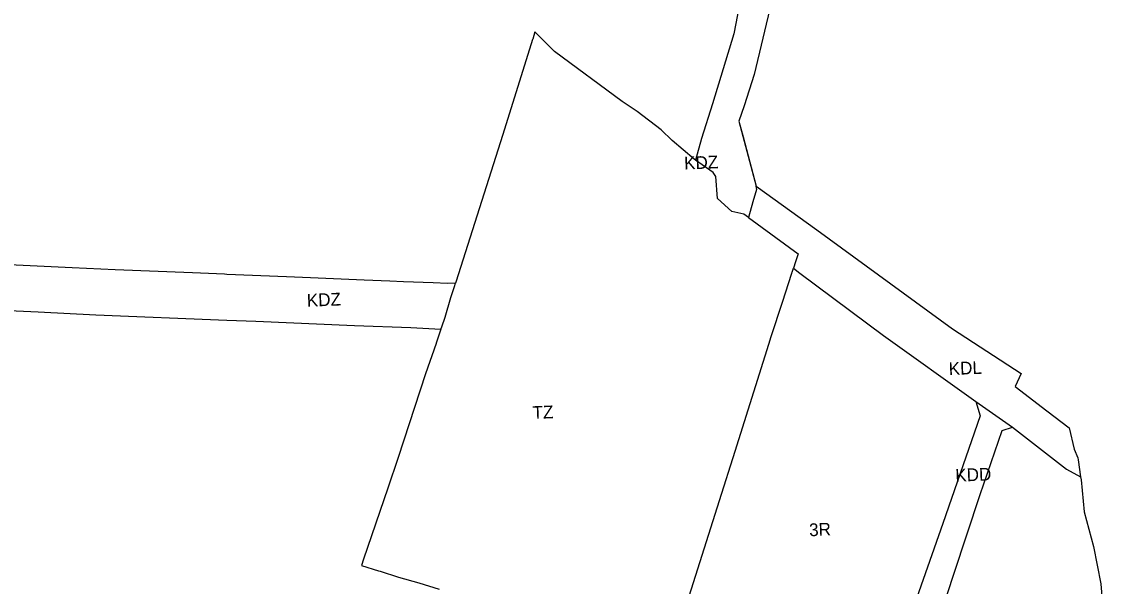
# Model space of a CAD drawing. Extents: x 7417062 to 7419348, y 5549957 to 5551711.
# Drawn here: x 7418374 to 7418967, y 5550811 to 5551121 of the extents above; entities that cross this region are included whole.
import ezdxf

# ---------------------------------------------------------------- set-up
doc = ezdxf.new("R2010")
doc.units = 0
for name, color, linetype in [('GRANICA_PLANU_po_wejsciu_MYDLNIKI', 7, 'Continuous'), ('linie_rozgraniczające_po_wejsciu_MYDLNIKI', 7, 'Continuous'), ('oznaczenia_przeznaczen_po_wejsciu_MYDLNIKI', 7, 'Continuous')]:
    doc.layers.add(name, color=color, linetype=linetype)

msp = doc.modelspace()

# ---------------------------------------------------------------- linework, layer by layer
at = {"layer": 'GRANICA_PLANU_po_wejsciu_MYDLNIKI'}
msp.add_lwpolyline([(7418785.33, 5551131.44), (7418775.9, 5551091.48), (7418770.4, 5551074.37), (7418767.45, 5551065.94), (7418769.76, 5551057.22), (7418776.89, 5551030.31), (7418776.92, 5551030.17), (7418810.32, 5551006.33), (7418884.63, 5550951.85), (7418922.29, 5550927.45), (7418919.04, 5550920.35), (7418936.52, 5550906.96), (7418948.63, 5550897.68), (7418951.38, 5550885.85), (7418953.53, 5550881.09), (7418953.68, 5550880.07), (7418955.01, 5550870.78), (7418955.26, 5550869.02), (7418957.01, 5550851.46), (7418962.06, 5550832.43), (7418966.12, 5550812.07), (7418966.93, 5550800.53)], dxfattribs=at)
at = {"layer": 'linie_rozgraniczające_po_wejsciu_MYDLNIKI'}
for p, q in [((7418772.3, 5551154.18), (7418764.79, 5551113.79)), ((7418785.33, 5551131.44), (7418775.9, 5551091.48)), ((7418655.58, 5551114.86), (7418654.33, 5551110.88)), ((7418666.39, 5551104.09), (7418655.58, 5551114.86)), ((7418764.79, 5551113.79), (7418752.93, 5551075.39)), ((7418654.3, 5551110.78), (7418638, 5551058.56)), ((7418654.33, 5551110.88), (7418654.3, 5551110.78)), ((7418703.44, 5551076.63), (7418666.39, 5551104.09)), ((7418775.9, 5551091.48), (7418770.4, 5551074.37)), ((7418711.58, 5551071.21), (7418703.44, 5551076.63)), ((7418724.79, 5551061.16), (7418711.58, 5551071.21)), ((7418752.93, 5551075.39), (7418746.95, 5551056.45)), ((7418770.4, 5551074.37), (7418767.45, 5551065.94)), ((7418767.45, 5551065.94), (7418776.89, 5551030.31)), ((7418730.78, 5551055.33), (7418724.79, 5551061.16)), ((7418638, 5551058.56), (7418612.19, 5550977.63)), ((7418742.94, 5551045.01), (7418730.78, 5551055.33)), ((7418746.95, 5551056.45), (7418743.67, 5551044.5)), ((7418743.67, 5551044.5), (7418742.94, 5551045.01)), ((7418753.29, 5551037.77), (7418743.67, 5551044.5)), ((7418754.75, 5551035.55), (7418753.29, 5551037.77)), ((7418755.66, 5551023.41), (7418754.75, 5551035.55)), ((7418776.92, 5551030.17), (7418776.74, 5551030.3)), ((7418776.74, 5551030.3), (7418777.1, 5551028.48)), ((7418776.89, 5551030.31), (7418776.92, 5551030.17)), ((7418776.92, 5551030.17), (7418776.93, 5551030.14)), ((7418776.93, 5551030.14), (7418810.32, 5551006.33)), ((7418777.1, 5551028.48), (7418775.15, 5551021.6)), ((7418763.61, 5551016.31), (7418755.66, 5551023.41)), ((7418775.15, 5551021.6), (7418772.73, 5551013.07)), ((7418770.16, 5551014.95), (7418763.61, 5551016.31)), ((7418772.73, 5551013.07), (7418770.16, 5551014.95)), ((7418772.73, 5551013.07), (7418800.03, 5550993.08)), ((7418810.32, 5551006.33), (7418884.63, 5550951.85)), ((7418798.58, 5550988.66), (7418797.43, 5550985.16)), ((7418800.03, 5550993.08), (7418798.58, 5550988.66)), ((7418401.67, 5550985.46), (7418367.16, 5550987.05)), ((7418425.27, 5550984.37), (7418401.67, 5550985.46)), ((7418467.61, 5550982.59), (7418425.27, 5550984.37)), ((7418485.24, 5550981.85), (7418467.61, 5550982.59)), ((7418791.33, 5550966.51), (7418796.57, 5550982.53)), ((7418796.57, 5550982.53), (7418796.61, 5550982.64)), ((7418796.61, 5550982.64), (7418796.73, 5550983.02)), ((7418796.73, 5550983.02), (7418797.43, 5550985.16)), ((7418797.43, 5550985.16), (7418800.86, 5550982.44)), ((7418800.86, 5550982.44), (7418846.82, 5550948.28)), ((7418486.52, 5550981.8), (7418485.24, 5550981.85)), ((7418519.27, 5550980.42), (7418486.52, 5550981.8)), ((7418532.49, 5550979.87), (7418519.27, 5550980.42)), ((7418561.89, 5550978.64), (7418532.49, 5550979.87)), ((7418576.01, 5550978.07), (7418561.89, 5550978.64)), ((7418583.4, 5550977.77), (7418576.01, 5550978.07)), ((7418599.8, 5550977.11), (7418583.4, 5550977.77)), ((7418607.62, 5550976.89), (7418599.8, 5550977.11)), ((7418611.96, 5550976.91), (7418607.62, 5550976.89)), ((7418611.38, 5550975.08), (7418611.96, 5550976.91)), ((7418612.16, 5550977.55), (7418611.96, 5550976.91)), ((7418612.19, 5550977.63), (7418612.16, 5550977.55)), ((7418609.5, 5550969.18), (7418611.38, 5550975.08)), ((7418606.27, 5550958.25), (7418609.5, 5550969.18)), ((7418785.16, 5550947.7), (7418791.33, 5550966.51)), ((7418366.87, 5550962.04), (7418382.91, 5550961.3)), ((7418382.91, 5550961.3), (7418414.64, 5550959.57)), ((7418414.64, 5550959.57), (7418486.48, 5550956.74)), ((7418604.44, 5550952.95), (7418606.27, 5550958.25)), ((7418486.48, 5550956.74), (7418502.35, 5550956.11)), ((7418502.35, 5550956.11), (7418556.54, 5550953.84)), ((7418556.54, 5550953.84), (7418556.56, 5550953.84)), ((7418556.56, 5550953.84), (7418587.48, 5550952.59)), ((7418587.48, 5550952.59), (7418604, 5550951.67)), ((7418604, 5550951.67), (7418604.44, 5550952.95)), ((7418604, 5550951.67), (7418601.36, 5550944.02)), ((7418783.86, 5550943.54), (7418785.16, 5550947.7)), ((7418846.82, 5550948.28), (7418897.43, 5550912)), ((7418884.63, 5550951.85), (7418884.63, 5550951.85)), ((7418884.63, 5550951.85), (7418884.63, 5550951.85)), ((7418884.63, 5550951.85), (7418922.29, 5550927.45)), ((7418601.33, 5550943.94), (7418595.57, 5550927.24)), ((7418601.43, 5550944.03), (7418601.33, 5550943.94)), ((7418601.36, 5550944.02), (7418601.43, 5550944.03)), ((7418765.47, 5550884.8), (7418783.86, 5550943.54)), ((7418595.57, 5550927.24), (7418580.51, 5550881.35)), ((7418922.29, 5550927.45), (7418922.29, 5550927.45)), ((7418919.04, 5550920.35), (7418936.52, 5550906.96)), ((7418897.43, 5550912), (7418899.88, 5550904.25)), ((7418897.43, 5550912), (7418917.63, 5550898.07)), ((7418936.52, 5550906.96), (7418948.63, 5550897.68)), ((7418899.88, 5550904.25), (7418879.3, 5550845.1)), ((7418899.8, 5550860.95), (7418911.93, 5550896.2)), ((7418911.93, 5550896.2), (7418917.63, 5550898.07)), ((7418917.63, 5550898.07), (7418947.24, 5550874.91)), ((7418948.63, 5550897.68), (7418951.38, 5550885.85)), ((7418580.51, 5550881.35), (7418574.84, 5550864.58)), ((7418756.81, 5550857.8), (7418765.47, 5550884.8)), ((7418951.38, 5550885.85), (7418951.38, 5550885.85)), ((7418951.38, 5550885.85), (7418953.53, 5550881.09)), ((7418953.53, 5550881.09), (7418953.68, 5550880.07)), ((7418953.68, 5550880.07), (7418955.01, 5550870.78)), ((7418947.24, 5550874.91), (7418955.01, 5550870.78)), ((7418955.01, 5550870.78), (7418955.26, 5550869.02)), ((7418574.84, 5550864.58), (7418561.55, 5550825.62)), ((7418955.26, 5550869.02), (7418957.01, 5550851.46)), ((7418742.52, 5550812.78), (7418756.81, 5550857.8)), ((7418885.44, 5550817.28), (7418899.8, 5550860.95)), ((7418957.01, 5550851.46), (7418957.01, 5550851.46)), ((7418957.01, 5550851.46), (7418962.06, 5550832.43)), ((7418879.3, 5550845.1), (7418853.95, 5550772.84)), ((7418962.06, 5550832.43), (7418966.12, 5550812.07)), ((7418561.55, 5550825.62), (7418560.33, 5550822.05)), ((7418560.33, 5550822.05), (7418569.65, 5550819.16)), ((7418569.65, 5550819.16), (7418570.62, 5550818.88)), ((7418570.62, 5550818.88), (7418580.76, 5550815.76)), ((7418865.61, 5550756.51), (7418885.44, 5550817.28)), ((7418580.76, 5550815.76), (7418591.95, 5550812.48)), ((7418591.95, 5550812.48), (7418603.02, 5550809.15)), ((7418729.15, 5550769.84), (7418742.52, 5550812.78)), ((7418966.12, 5550812.07), (7418966.93, 5550800.53))]:
    msp.add_line(p, q, dxfattribs=at)
msp.add_lwpolyline([(7418922.29, 5550927.45), (7418919.04, 5550920.35)], dxfattribs=at)

# ---------------------------------------------------------------- texts
at = {"layer": 'oznaczenia_przeznaczen_po_wejsciu_MYDLNIKI'}
for s, p in [('KDZ', (7418737.55, 5551039.33)), ('KDZ', (7418530.53, 5550964.04)), ('KDL', (7418882.74, 5550926.54)), ('TZ', (7418654.42, 5550902.45)), ('KDD', (7418886.36, 5550868.02)), ('3R', (7418806.14, 5550838.1))]:
    msp.add_text(s, height=7, rotation=2.32296, dxfattribs=at).set_placement(p)

doc.saveas('drawing.dxf')
